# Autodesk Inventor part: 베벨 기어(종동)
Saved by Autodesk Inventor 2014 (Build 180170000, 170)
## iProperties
Created: 2026-01
Part Number: 베벨 기어(종동)
Material: 일반
Document SubType Name: Modeling
Designer: dg
Density: 1 g/cm^3
Appearance: 기본값
Author: dg
Author: jhkim
Creation Date: 2026-01-09
Sending System: Autodesk Inventor 2026
Preprocessor: ST-DEVELOPER v20.1
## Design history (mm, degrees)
node "베벨 기어(종동)1"
body "Solid1"
node "기준1"
